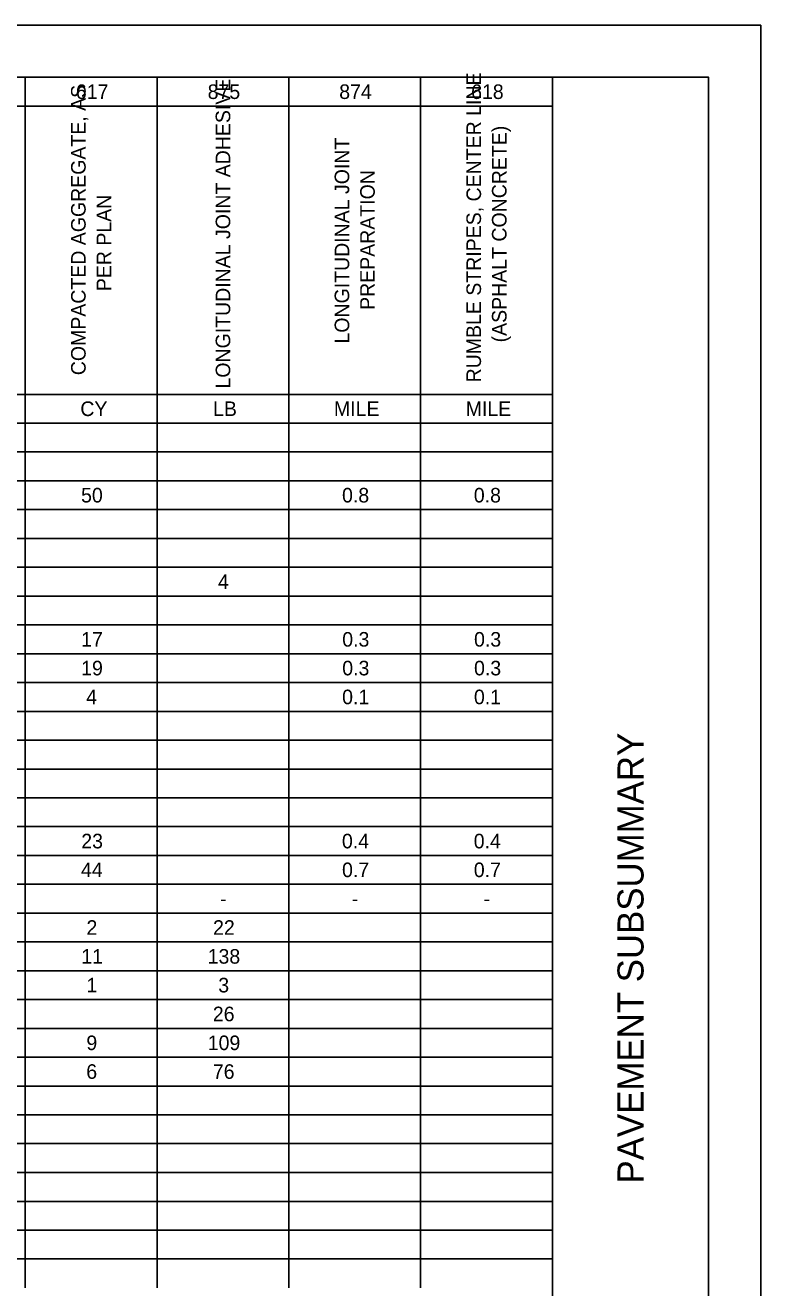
# Model space of a CAD drawing. Extents: x 0 to 34, y 0 to 22.
# Drawn here: x 26.94 to 34, y 9.88 to 22 of the extents above; entities that cross this region are included whole.
import ezdxf

# ---------------------------------------------------------------- set-up
doc = ezdxf.new("R2010")
doc.units = 0
for name, color, linetype in [('SH_Border', 7, 'Continuous'), ('SH_Cut_Line', 7, 'Continuous'), ('SH_Data', 7, 'Continuous'), ('SH_Text', 7, 'Continuous')]:
    doc.layers.add(name, color=color, linetype=linetype)

msp = doc.modelspace()

# ---------------------------------------------------------------- linework, layer by layer
at = {"layer": 'SH_Border'}
msp.add_line((32, 0.5), (32, 21.5), dxfattribs=at)
msp.add_lwpolyline([(1.5, 21.5), (33.5, 21.5), (33.5, 0.5), (1.5, 0.5)], close=True, dxfattribs=at)
at = {"layer": 'SH_Cut_Line'}
msp.add_lwpolyline([(0, 0), (34, 0), (34, 22), (0, 22)], close=True, dxfattribs=at)
at = {"layer": 'SH_Text'}
for p, q in [((25.675, 21.5), (26.94, 21.5)), ((26.94, 21.5), (28.205, 21.5)), ((26.94, 21.5), (26.94, 21.223)), ((28.205, 21.5), (29.47, 21.5)), ((28.205, 21.5), (28.205, 21.223)), ((29.47, 21.5), (30.735, 21.5)), ((29.47, 21.5), (29.47, 21.223)), ((30.735, 21.5), (32, 21.5)), ((30.735, 21.5), (30.735, 21.223)), ((32, 21.5), (32, 21.223)), ((25.675, 21.223), (26.94, 21.223)), ((26.94, 21.223), (28.205, 21.223)), ((26.94, 21.223), (26.94, 20.947)), ((28.205, 21.223), (29.47, 21.223)), ((28.205, 21.223), (28.205, 20.947)), ((29.47, 21.223), (30.735, 21.223)), ((29.47, 21.223), (29.47, 20.947)), ((30.735, 21.223), (32, 21.223)), ((30.735, 21.223), (30.735, 20.947)), ((32, 21.223), (32, 20.947)), ((26.94, 20.947), (26.94, 20.67)), ((28.205, 20.947), (28.205, 20.67)), ((29.47, 20.947), (29.47, 20.67)), ((30.735, 20.947), (30.735, 20.67)), ((32, 20.947), (32, 20.67)), ((26.94, 20.67), (26.94, 20.393)), ((28.205, 20.67), (28.205, 20.393)), ((29.47, 20.67), (29.47, 20.393)), ((30.735, 20.67), (30.735, 20.393)), ((32, 20.67), (32, 20.393)), ((26.94, 20.393), (26.94, 20.116)), ((28.205, 20.393), (28.205, 20.116)), ((29.47, 20.393), (29.47, 20.116)), ((30.735, 20.393), (30.735, 20.116)), ((32, 20.393), (32, 20.116)), ((26.94, 20.116), (26.94, 19.84)), ((28.205, 20.116), (28.205, 19.84)), ((29.47, 20.116), (29.47, 19.84)), ((30.735, 20.116), (30.735, 19.84)), ((32, 20.116), (32, 19.84)), ((26.94, 19.84), (26.94, 19.563)), ((28.205, 19.84), (28.205, 19.563)), ((29.47, 19.84), (29.47, 19.563)), ((30.735, 19.84), (30.735, 19.563)), ((32, 19.84), (32, 19.563)), ((26.94, 19.563), (26.94, 19.01)), ((28.205, 19.563), (28.205, 19.01)), ((29.47, 19.563), (29.47, 19.01)), ((30.735, 19.563), (30.735, 19.01)), ((32, 19.563), (32, 19.01)), ((26.94, 19.01), (26.94, 18.18)), ((28.205, 19.01), (28.205, 18.18)), ((29.47, 19.01), (29.47, 18.18)), ((30.735, 19.01), (30.735, 18.18)), ((32, 19.01), (32, 18.18)), ((25.675, 18.456), (26.94, 18.456)), ((26.94, 18.456), (28.205, 18.456)), ((28.205, 18.456), (29.47, 18.456)), ((29.47, 18.456), (30.735, 18.456)), ((30.735, 18.456), (32, 18.456)), ((25.675, 18.18), (26.94, 18.18)), ((26.94, 18.18), (28.205, 18.18)), ((26.94, 18.18), (26.94, 17.349)), ((28.205, 18.18), (29.47, 18.18)), ((28.205, 18.18), (28.205, 17.349)), ((29.47, 18.18), (30.735, 18.18)), ((29.47, 18.18), (29.47, 17.349)), ((30.735, 18.18), (32, 18.18)), ((30.735, 18.18), (30.735, 17.349)), ((32, 18.18), (32, 17.349)), ((25.675, 17.903), (26.94, 17.903)), ((26.94, 17.903), (28.205, 17.903)), ((28.205, 17.903), (29.47, 17.903)), ((29.47, 17.903), (30.735, 17.903)), ((30.735, 17.903), (32, 17.903)), ((25.675, 17.626), (26.94, 17.626)), ((26.94, 17.626), (28.205, 17.626)), ((28.205, 17.626), (29.47, 17.626)), ((29.47, 17.626), (30.735, 17.626)), ((30.735, 17.626), (32, 17.626)), ((25.675, 17.349), (26.94, 17.349)), ((26.94, 17.349), (28.205, 17.349)), ((26.94, 17.349), (26.94, 17.073)), ((28.205, 17.349), (29.47, 17.349)), ((28.205, 17.349), (28.205, 17.073)), ((29.47, 17.349), (30.735, 17.349)), ((29.47, 17.349), (29.47, 17.073)), ((30.735, 17.349), (32, 17.349)), ((30.735, 17.349), (30.735, 17.073)), ((32, 17.349), (32, 17.073)), ((25.675, 17.073), (26.94, 17.073)), ((26.94, 17.073), (28.205, 17.073)), ((26.94, 17.073), (26.94, 15.966)), ((28.205, 17.073), (29.47, 17.073)), ((28.205, 17.073), (28.205, 15.966)), ((29.47, 17.073), (30.735, 17.073)), ((29.47, 17.073), (29.47, 15.966)), ((30.735, 17.073), (32, 17.073)), ((30.735, 17.073), (30.735, 15.966)), ((32, 17.073), (32, 15.966)), ((25.675, 16.796), (26.94, 16.796)), ((26.94, 16.796), (28.205, 16.796)), ((28.205, 16.796), (29.47, 16.796)), ((29.47, 16.796), (30.735, 16.796)), ((30.735, 16.796), (32, 16.796)), ((25.675, 16.519), (26.94, 16.519)), ((26.94, 16.519), (28.205, 16.519)), ((28.205, 16.519), (29.47, 16.519)), ((29.47, 16.519), (30.735, 16.519)), ((30.735, 16.519), (32, 16.519)), ((25.675, 16.243), (26.94, 16.243)), ((26.94, 16.243), (28.205, 16.243)), ((28.205, 16.243), (29.47, 16.243)), ((29.47, 16.243), (30.735, 16.243)), ((30.735, 16.243), (32, 16.243)), ((25.675, 15.966), (26.94, 15.966)), ((26.94, 15.966), (28.205, 15.966)), ((26.94, 15.966), (26.94, 15.689)), ((28.205, 15.966), (29.47, 15.966)), ((28.205, 15.966), (28.205, 15.689)), ((29.47, 15.966), (30.735, 15.966)), ((29.47, 15.966), (29.47, 15.689)), ((30.735, 15.966), (32, 15.966)), ((30.735, 15.966), (30.735, 15.689)), ((32, 15.966), (32, 15.689)), ((25.675, 15.689), (26.94, 15.689)), ((26.94, 15.689), (28.205, 15.689)), ((26.94, 15.689), (26.94, 15.136)), ((28.205, 15.689), (29.47, 15.689)), ((28.205, 15.689), (28.205, 15.136)), ((29.47, 15.689), (30.735, 15.689)), ((29.47, 15.689), (29.47, 15.136)), ((30.735, 15.689), (32, 15.689)), ((30.735, 15.689), (30.735, 15.136)), ((32, 15.689), (32, 15.136)), ((25.675, 15.412), (26.94, 15.412)), ((26.94, 15.412), (28.205, 15.412)), ((28.205, 15.412), (29.47, 15.412)), ((29.47, 15.412), (30.735, 15.412)), ((30.735, 15.412), (32, 15.412)), ((25.675, 15.136), (26.94, 15.136)), ((26.94, 15.136), (28.205, 15.136)), ((26.94, 15.136), (26.94, 14.582)), ((28.205, 15.136), (29.47, 15.136)), ((28.205, 15.136), (28.205, 14.582)), ((29.47, 15.136), (30.735, 15.136)), ((29.47, 15.136), (29.47, 14.582)), ((30.735, 15.136), (32, 15.136)), ((30.735, 15.136), (30.735, 14.582)), ((32, 15.136), (32, 14.582)), ((25.675, 14.859), (26.94, 14.859)), ((26.94, 14.859), (28.205, 14.859)), ((28.205, 14.859), (29.47, 14.859)), ((29.47, 14.859), (30.735, 14.859)), ((30.735, 14.859), (32, 14.859)), ((25.675, 14.582), (26.94, 14.582)), ((26.94, 14.582), (28.205, 14.582)), ((26.94, 14.582), (26.94, 14.306)), ((28.205, 14.582), (29.47, 14.582)), ((28.205, 14.582), (28.205, 14.306)), ((29.47, 14.582), (30.735, 14.582)), ((29.47, 14.582), (29.47, 14.306)), ((30.735, 14.582), (32, 14.582)), ((30.735, 14.582), (30.735, 14.306)), ((32, 14.582), (32, 14.306)), ((25.675, 14.306), (26.94, 14.306)), ((26.94, 14.306), (28.205, 14.306)), ((26.94, 14.306), (26.94, 13.752)), ((28.205, 14.306), (29.47, 14.306)), ((28.205, 14.306), (28.205, 13.752)), ((29.47, 14.306), (30.735, 14.306)), ((29.47, 14.306), (29.47, 13.752)), ((30.735, 14.306), (32, 14.306)), ((30.735, 14.306), (30.735, 13.752)), ((32, 14.306), (32, 13.752)), ((25.675, 14.029), (26.94, 14.029)), ((26.94, 14.029), (28.205, 14.029)), ((28.205, 14.029), (29.47, 14.029)), ((29.47, 14.029), (30.735, 14.029)), ((30.735, 14.029), (32, 14.029)), ((25.675, 13.752), (26.94, 13.752)), ((26.94, 13.752), (28.205, 13.752)), ((26.94, 13.752), (26.94, 13.476)), ((28.205, 13.752), (29.47, 13.752)), ((28.205, 13.752), (28.205, 13.476)), ((29.47, 13.752), (30.735, 13.752)), ((29.47, 13.752), (29.47, 13.476)), ((30.735, 13.752), (32, 13.752)), ((30.735, 13.752), (30.735, 13.476)), ((32, 13.752), (32, 13.476)), ((25.675, 13.476), (26.94, 13.476)), ((26.94, 13.476), (28.205, 13.476)), ((26.94, 13.476), (26.94, 12.645)), ((28.205, 13.476), (29.47, 13.476)), ((28.205, 13.476), (28.205, 12.645)), ((29.47, 13.476), (30.735, 13.476)), ((29.47, 13.476), (29.47, 12.645)), ((30.735, 13.476), (32, 13.476)), ((30.735, 13.476), (30.735, 12.645)), ((32, 13.476), (32, 12.645)), ((25.675, 13.199), (26.94, 13.199)), ((26.94, 13.199), (28.205, 13.199)), ((28.205, 13.199), (29.47, 13.199)), ((29.47, 13.199), (30.735, 13.199)), ((30.735, 13.199), (32, 13.199)), ((25.675, 12.922), (26.94, 12.922)), ((26.94, 12.922), (28.205, 12.922)), ((28.205, 12.922), (29.47, 12.922)), ((29.47, 12.922), (30.735, 12.922)), ((30.735, 12.922), (32, 12.922)), ((25.675, 12.645), (26.94, 12.645)), ((26.94, 12.645), (28.205, 12.645)), ((26.94, 12.645), (26.94, 12.369)), ((28.205, 12.645), (29.47, 12.645)), ((28.205, 12.645), (28.205, 12.369)), ((29.47, 12.645), (30.735, 12.645)), ((29.47, 12.645), (29.47, 12.369)), ((30.735, 12.645), (32, 12.645)), ((30.735, 12.645), (30.735, 12.369)), ((32, 12.645), (32, 12.369)), ((25.675, 12.369), (26.94, 12.369)), ((26.94, 12.369), (28.205, 12.369)), ((26.94, 12.369), (26.94, 12.092)), ((28.205, 12.369), (29.47, 12.369)), ((28.205, 12.369), (28.205, 12.092)), ((29.47, 12.369), (30.735, 12.369)), ((29.47, 12.369), (29.47, 12.092)), ((30.735, 12.369), (32, 12.369)), ((30.735, 12.369), (30.735, 12.092)), ((32, 12.369), (32, 12.092)), ((25.675, 12.092), (26.94, 12.092)), ((26.94, 12.092), (28.205, 12.092)), ((26.94, 12.092), (26.94, 11.262)), ((28.205, 12.092), (29.47, 12.092)), ((28.205, 12.092), (28.205, 11.262)), ((29.47, 12.092), (30.735, 12.092)), ((29.47, 12.092), (29.47, 11.262)), ((30.735, 12.092), (32, 12.092)), ((30.735, 12.092), (30.735, 11.262)), ((32, 12.092), (32, 11.262)), ((25.675, 11.815), (26.94, 11.815)), ((26.94, 11.815), (28.205, 11.815)), ((28.205, 11.815), (29.47, 11.815)), ((29.47, 11.815), (30.735, 11.815)), ((30.735, 11.815), (32, 11.815)), ((25.675, 11.539), (26.94, 11.539)), ((26.94, 11.539), (28.205, 11.539)), ((28.205, 11.539), (29.47, 11.539)), ((29.47, 11.539), (30.735, 11.539)), ((30.735, 11.539), (32, 11.539)), ((25.675, 11.262), (26.94, 11.262)), ((26.94, 11.262), (28.205, 11.262)), ((26.94, 11.262), (26.94, 10.708)), ((28.205, 11.262), (29.47, 11.262)), ((28.205, 11.262), (28.205, 10.708)), ((29.47, 11.262), (30.735, 11.262)), ((29.47, 11.262), (29.47, 10.708)), ((30.735, 11.262), (32, 11.262)), ((30.735, 11.262), (30.735, 10.708)), ((32, 11.262), (32, 10.708)), ((25.675, 10.985), (26.94, 10.985)), ((26.94, 10.985), (28.205, 10.985)), ((28.205, 10.985), (29.47, 10.985)), ((29.47, 10.985), (30.735, 10.985)), ((30.735, 10.985), (32, 10.985)), ((25.675, 10.708), (26.94, 10.708)), ((26.94, 10.708), (28.205, 10.708)), ((26.94, 10.708), (26.94, 9.878)), ((28.205, 10.708), (29.47, 10.708)), ((28.205, 10.708), (28.205, 9.878)), ((29.47, 10.708), (30.735, 10.708)), ((29.47, 10.708), (29.47, 9.878)), ((30.735, 10.708), (32, 10.708)), ((30.735, 10.708), (30.735, 9.878)), ((32, 10.708), (32, 9.878)), ((25.675, 10.432), (26.94, 10.432)), ((26.94, 10.432), (28.205, 10.432)), ((28.205, 10.432), (29.47, 10.432)), ((29.47, 10.432), (30.735, 10.432)), ((30.735, 10.432), (32, 10.432)), ((25.675, 10.155), (26.94, 10.155)), ((26.94, 10.155), (28.205, 10.155)), ((28.205, 10.155), (29.47, 10.155)), ((29.47, 10.155), (30.735, 10.155)), ((30.735, 10.155), (32, 10.155))]:
    msp.add_line(p, q, dxfattribs=at)

# ---------------------------------------------------------------- texts
at = {"layer": 'SH_Data'}
msp.add_text('PAVEMENT SUBSUMMARY', height=0.25, rotation=90, dxfattribs=at).set_placement((32.875, 10.879))
at = {"layer": 'SH_Text'}
for s, p in [('LONGITUDINAL JOINT ADHESIVE', (28.908, 18.512)), ('RUMBLE STRIPES, CENTER LINE ', (31.315, 18.571)), ('COMPACTED AGGREGATE, AS ', (27.52, 18.64)), ('(ASPHALT CONCRETE)', (31.56, 18.955)), ('LONGITUDINAL JOINT ', (30.05, 18.944)), ('PREPARATION', (30.295, 19.267)), ('PER PLAN', (27.765, 19.447))]:
    msp.add_text(s, height=0.14, rotation=90, dxfattribs=at).set_placement(p)
for s, p in [('617', (27.426, 21.292)), ('875', (28.691, 21.292)), ('874', (29.954, 21.292)), ('618', (31.22, 21.292)), ('CY', (27.469, 18.248)), ('LB', (28.743, 18.248)), ('MILE', (29.903, 18.248)), ('MILE', (31.168, 18.248)), ('50', (27.476, 17.418)), ('0.8', (29.981, 17.418)), ('0.8', (31.246, 17.418)), ('4', (28.79, 16.588)), ('17', (27.477, 16.034)), ('0.3', (29.983, 16.034)), ('0.3', (31.248, 16.034)), ('19', (27.477, 15.758)), ('0.3', (29.983, 15.758)), ('0.3', (31.248, 15.758)), ('4', (27.525, 15.481)), ('0.1', (29.982, 15.481)), ('0.1', (31.247, 15.481)), ('23', (27.478, 14.097)), ('0.4', (29.98, 14.097)), ('0.4', (31.245, 14.097)), ('44', (27.475, 13.821)), ('0.7', (29.981, 13.821)), ('0.7', (31.246, 13.821)), ('-', (28.811, 13.544)), ('-', (30.075, 13.544)), ('-', (31.34, 13.544)), ('2', (27.528, 13.267)), ('22', (28.743, 13.267)), ('11', (27.478, 12.99)), ('138', (28.691, 12.99)), ('1', (27.528, 12.714)), ('3', (28.793, 12.714)), ('26', (28.741, 12.437)), ('9', (27.527, 12.16)), ('109', (28.692, 12.16)), ('6', (27.526, 11.884)), ('76', (28.741, 11.884))]:
    msp.add_text(s, height=0.14, dxfattribs=at).set_placement(p)

doc.saveas('drawing.dxf')
